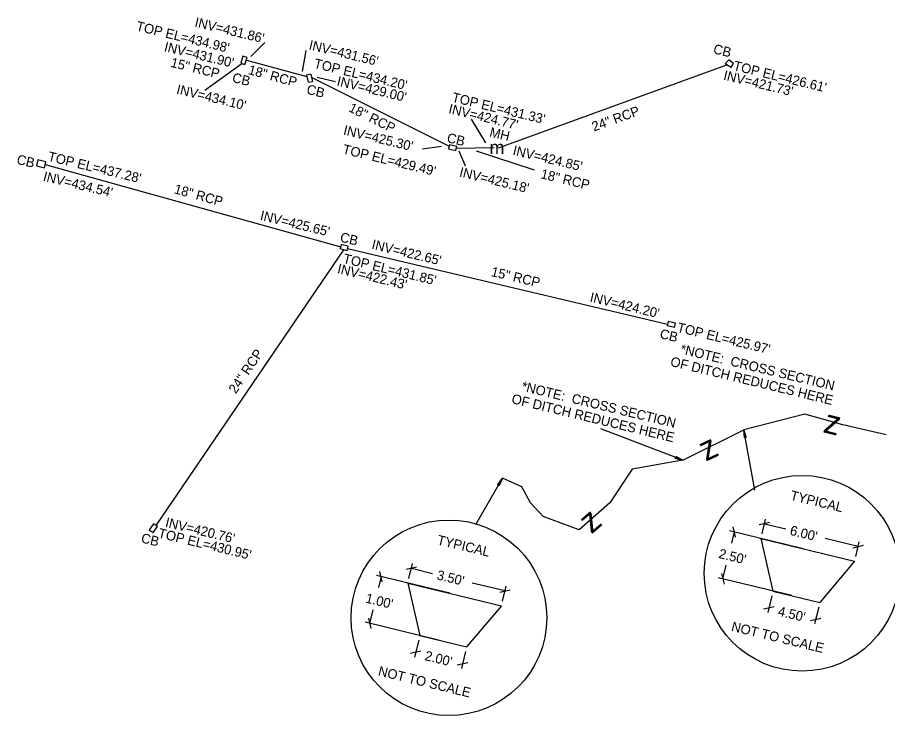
# Model space of a CAD drawing. Extents: x 1975859 to 1978323, y 778892 to 782836.
# Drawn here: x 1977393.8 to 1977755, y 779966.5 to 780256.5 of the extents above; entities that cross this region are included whole.
import ezdxf

# ---------------------------------------------------------------- set-up
doc = ezdxf.new("R2010")
doc.units = 0
for name, color, linetype in [('Exist Structure Minor Catch Basin', 7, 'Continuous'), ('Exist Structure Minor Catch Basin Text', 7, 'Continuous'), ('Exist Structure Minor Catch Basin Top Elevation', 7, 'Continuous'), ('Exist Structure Minor Pipes RCP 15 Inch', 7, 'Continuous'), ('Exist Structure Minor Pipes RCP 15 Inch Invert', 7, 'Continuous'), ('Exist Structure Minor Pipes RCP 15 Inch Text', 7, 'Continuous'), ('Exist Structure Minor Pipes RCP 18 Inch', 7, 'Continuous'), ('Exist Structure Minor Pipes RCP 18 Inch Invert', 7, 'Continuous'), ('Exist Structure Minor Pipes RCP 18 Inch Leader', 7, 'Continuous'), ('Exist Structure Minor Pipes RCP 18 Inch SizeText', 7, 'Continuous'), ('Exist Structure Minor Pipes RCP 18 Inch Text', 7, 'Continuous'), ('Exist Structure Minor Pipes RCP 24 Inch', 7, 'Continuous'), ('Exist Structure Minor Pipes RCP 24 Inch Invert', 7, 'Continuous'), ('Exist Structure Minor Pipes RCP 24 Inch Text', 7, 'Continuous'), ('Exist Structure Minor Storm Sewer Manhole CELL', 7, 'Continuous'), ('Exist Structure Minor Storm Sewer Manhole Text', 7, 'Continuous'), ('Exist Structure Minor Storm Sewer Manhole Top Elevation', 7, 'Continuous'), ('Scratch_Level_8', 7, 'Continuous')]:
    doc.layers.add(name, color=color, linetype=linetype)

msp = doc.modelspace()

# ---------------------------------------------------------------- linework, layer by layer
at = {"layer": 'Exist Structure Minor Catch Basin'}
for p, q in [((1977487.39, 780240.38), (1977486.53, 780237.46)), ((1977690.04, 780235.63), (1977687.58, 780237.2)), ((1977515.66, 780232.92), (1977516.32, 780229.9)), ((1977573.18, 780203.68), (1977576.18, 780202.99)), ((1977402.37, 780197.29), (1977401.8, 780194.88)), ((1977530.73, 780159.58), (1977527.73, 780160.29)), ((1977666.47, 780127.68), (1977663.48, 780128.42)), ((1977450.15, 780042.53), (1977451.93, 780045.03))]:
    msp.add_line(p, q, dxfattribs=at)
for points in [[(1977486.53, 780237.46), (1977488.22, 780236.92), (1977489.17, 780239.82), (1977487.39, 780240.38)], [(1977690.04, 780235.63), (1977691.03, 780237.33), (1977689.11, 780238.91), (1977687.58, 780237.2)], [(1977515.66, 780232.92), (1977513.82, 780232.52), (1977514.44, 780229.54), (1977516.32, 780229.9)], [(1977573.18, 780203.68), (1977572.78, 780201.9), (1977575.76, 780201.22), (1977576.18, 780202.99)], [(1977401.8, 780194.88), (1977405.1, 780194.06), (1977405.71, 780196.43), (1977402.37, 780197.29)], [(1977530.73, 780159.58), (1977531.14, 780161.45), (1977528.19, 780162.15), (1977527.73, 780160.29)], [(1977666.47, 780127.68), (1977666.91, 780129.55), (1977663.95, 780130.21), (1977663.48, 780128.42)], [(1977451.93, 780045.03), (1977450.38, 780046.19), (1977448.58, 780043.69), (1977450.15, 780042.53)]]:
    msp.add_lwpolyline(points, dxfattribs=at)
at = {"layer": 'Exist Structure Minor Pipes RCP 15 Inch'}
for p, q in [((1977471.64, 780226.29), (1977487, 780237.36)), ((1977663.62, 780128.87), (1977530.86, 780160.3))]:
    msp.add_line(p, q, dxfattribs=at)
at = {"layer": 'Exist Structure Minor Pipes RCP 18 Inch'}
for p, q in [((1977488.87, 780238.76), (1977513.94, 780231.92)), ((1977516.02, 780231.5), (1977573.03, 780202.94)), ((1977575.97, 780202.13), (1977591.66, 780202.39)), ((1977405.32, 780195.31), (1977528.02, 780161.12))]:
    msp.add_line(p, q, dxfattribs=at)
at = {"layer": 'Exist Structure Minor Pipes RCP 18 Inch Leader'}
for points in [[(1977490.68, 780240.3), (1977496.46, 780246.07)], [(1977512.16, 780234.03), (1977513.69, 780242.77)], [(1977518.23, 780231.69), (1977525.82, 780229.83)], [(1977588.19, 780204.44), (1977582.34, 780214.22)], [(1977569.85, 780202.88), (1977561.92, 780201.81)], [(1977577.07, 780201.1), (1977579.7, 780194.77)], [(1977584.26, 780201.07), (1977608.35, 780193.15)]]:
    msp.add_lwpolyline(points, dxfattribs=at)
at = {"layer": 'Exist Structure Minor Pipes RCP 24 Inch'}
for p, q in [((1977593.48, 780202.32), (1977688.3, 780236.71)), ((1977529.14, 780159.92), (1977451.29, 780045.45))]:
    msp.add_line(p, q, dxfattribs=at)
at = {"layer": 'Scratch_Level_8'}
for p, q in [((1977670.05, 780072.53), (1977635.9, 780085.62)), ((1977670.05, 780072.53), (1977695.32, 780085.18)), ((1977699.84, 780060.11), (1977695.32, 780085.18)), ((1977696.17, 780081.97), (1977695.65, 780081.87)), ((1977695.69, 780081.92), (1977695.85, 780082.23)), ((1977695.85, 780082.23), (1977695.76, 780081.89)), ((1977695.85, 780082.23), (1977696.12, 780082)), ((1977695.85, 780082.23), (1977696.07, 780081.95)), ((1977695.85, 780082.23), (1977695.97, 780081.93)), ((1977695.85, 780082.23), (1977695.85, 780081.91)), ((1977666.86, 780073.47), (1977667.05, 780073.97)), ((1977667.25, 780073.61), (1977666.89, 780073.57)), ((1977667.25, 780073.61), (1977666.92, 780073.5)), ((1977667.25, 780073.61), (1977666.93, 780073.67)), ((1977667.25, 780073.61), (1977666.97, 780073.78)), ((1977667.25, 780073.61), (1977667.01, 780073.86)), ((1977667.07, 780073.91), (1977667.25, 780073.61)), ((1977584.03, 780045.88), (1977595.14, 780065.04)), ((1977593.71, 780062.04), (1977593.25, 780062.31)), ((1977593.31, 780062.32), (1977593.64, 780062.45)), ((1977593.64, 780062.45), (1977593.35, 780062.25)), ((1977593.64, 780062.45), (1977593.43, 780062.2)), ((1977593.64, 780062.45), (1977593.53, 780062.15)), ((1977593.64, 780062.45), (1977593.62, 780062.09)), ((1977593.64, 780062.45), (1977593.69, 780062.11)), ((1977706.06, 780046.67), (1977701.7, 780045.66)), ((1977702.86, 780041.98), (1977704.35, 780048.11)), ((1977703.88, 780046.17), (1977712.68, 780044.03)), ((1977719.89, 780035.79), (1977689.36, 780043.2)), ((1977691.31, 780042.73), (1977690.19, 780038.14)), ((1977691.81, 780040.55), (1977690.81, 780044.91)), ((1977702.39, 780040.04), (1977741.27, 780030.61)), ((1977702.39, 780040.04), (1977707.4, 780018.24)), ((1977742.75, 780036.74), (1977729.07, 780040.06)), ((1977741.74, 780032.55), (1977743.22, 780038.68)), ((1977740.57, 780036.24), (1977744.93, 780037.24)), ((1977559.51, 780028.17), (1977555.15, 780027.17)), ((1977556.31, 780023.49), (1977557.8, 780029.62)), ((1977557.33, 780027.67), (1977566.13, 780025.54)), ((1977686.59, 780023.29), (1977687.97, 780028.95)), ((1977741.27, 780030.61), (1977726.83, 780013.53)), ((1977573.34, 780017.3), (1977542.81, 780024.71)), ((1977544.76, 780024.23), (1977543.64, 780019.65)), ((1977545.26, 780022.06), (1977544.26, 780026.41)), ((1977686.09, 780025.47), (1977687.09, 780021.11)), ((1977555.84, 780021.55), (1977594.72, 780012.12)), ((1977555.84, 780021.55), (1977560.85, 779999.75)), ((1977596.2, 780018.25), (1977582.52, 780021.56)), ((1977715.17, 780016.36), (1977684.65, 780023.76)), ((1977594.02, 780017.74), (1977598.38, 780018.75)), ((1977595.19, 780014.06), (1977596.67, 780020.19)), ((1977707.4, 780018.24), (1977726.83, 780013.53)), ((1977706.93, 780016.3), (1977705.22, 780009.28)), ((1977540.04, 780004.8), (1977541.42, 780010.46)), ((1977594.72, 780012.12), (1977580.28, 779995.04)), ((1977707.87, 780011.72), (1977703.52, 780010.72)), ((1977726.36, 780011.59), (1977724.66, 780004.57)), ((1977539.54, 780006.98), (1977540.54, 780002.62)), ((1977722.95, 780006.01), (1977727.31, 780007.01)), ((1977568.62, 779997.87), (1977538.1, 780005.27)), ((1977560.85, 779999.75), (1977580.28, 779995.04)), ((1977560.38, 779997.81), (1977558.67, 779990.79)), ((1977561.32, 779993.23), (1977556.97, 779992.23)), ((1977579.81, 779993.09), (1977578.11, 779986.07)), ((1977576.4, 779987.52), (1977580.76, 779988.52))]:
    msp.add_line(p, q, dxfattribs=at)
for points in [[(1977754.38, 780083.09), (1977736.42, 780087.22), (1977720.65, 780091.73), (1977695.32, 780085.18)], [(1977696.09, 780082.11), (1977695.32, 780085.18), (1977696.17, 780081.97), (1977696.12, 780082), (1977696.09, 780082.11), (1977695.85, 780082.23), (1977695.67, 780082.03), (1977695.69, 780081.92), (1977695.65, 780081.87), (1977695.32, 780085.18), (1977695.67, 780082.03)], [(1977696.17, 780081.97), (1977696.22, 780082.21), (1977695.32, 780085.18), (1977695.52, 780082.08), (1977695.65, 780081.87)], [(1977695.58, 780081.98), (1977695.32, 780085.18), (1977696.2, 780082.09)], [(1977695.34, 780085.01), (1977695.34, 780085.09), (1977695.37, 780085), (1977695.39, 780084.91), (1977695.35, 780085), (1977695.35, 780084.92), (1977695.36, 780084.82), (1977695.37, 780084.91), (1977695.41, 780084.82), (1977695.43, 780084.73), (1977695.39, 780084.81), (1977695.37, 780084.73), (1977695.38, 780084.64), (1977695.4, 780084.72), (1977695.46, 780084.64), (1977695.48, 780084.55), (1977695.42, 780084.63), (1977695.39, 780084.54), (1977695.4, 780084.45), (1977695.44, 780084.54), (1977695.5, 780084.45), (1977695.52, 780084.36), (1977695.45, 780084.44), (1977695.41, 780084.36), (1977695.42, 780084.27), (1977695.47, 780084.35), (1977695.55, 780084.27), (1977695.57, 780084.18), (1977695.49, 780084.26), (1977695.44, 780084.17), (1977695.45, 780084.08), (1977695.5, 780084.17), (1977695.59, 780084.09), (1977695.61, 780084), (1977695.52, 780084.08), (1977695.46, 780083.99), (1977695.47, 780083.89), (1977695.54, 780083.98), (1977695.64, 780083.91), (1977695.66, 780083.82), (1977695.55, 780083.89), (1977695.48, 780083.8), (1977695.49, 780083.71), (1977695.57, 780083.8), (1977695.68, 780083.73), (1977695.7, 780083.64), (1977695.59, 780083.71), (1977695.5, 780083.61), (1977695.51, 780083.52), (1977695.6, 780083.62), (1977695.73, 780083.55), (1977695.75, 780083.46), (1977695.62, 780083.52), (1977695.52, 780083.43), (1977695.53, 780083.33), (1977695.64, 780083.43), (1977695.77, 780083.37), (1977695.8, 780083.27), (1977695.65, 780083.34), (1977695.54, 780083.24), (1977695.55, 780083.15), (1977695.67, 780083.25), (1977695.82, 780083.18), (1977695.84, 780083.09), (1977695.69, 780083.15), (1977695.56, 780083.06), (1977695.57, 780082.96), (1977695.7, 780083.06), (1977695.86, 780083), (1977695.89, 780082.91), (1977695.73, 780082.97), (1977695.58, 780082.87), (1977695.59, 780082.78), (1977695.74, 780082.88), (1977695.91, 780082.82), (1977695.93, 780082.73), (1977695.75, 780082.79), (1977695.6, 780082.68), (1977695.61, 780082.59), (1977695.77, 780082.69), (1977695.95, 780082.64), (1977695.98, 780082.55), (1977695.79, 780082.6), (1977695.62, 780082.5), (1977695.63, 780082.4), (1977695.8, 780082.51), (1977696, 780082.46), (1977696.02, 780082.37), (1977695.82, 780082.42), (1977695.64, 780082.31), (1977695.65, 780082.22), (1977695.84, 780082.33), (1977696.04, 780082.27), (1977696.07, 780082.18), (1977695.85, 780082.23), (1977695.66, 780082.13)], [(1977670.05, 780072.53), (1977649.01, 780068.8), (1977639.65, 780054.82), (1977627.03, 780043.71), (1977612.03, 780049.15), (1977606.75, 780054.93), (1977603.18, 780061.49), (1977595.14, 780065.04)], [(1977667.02, 780073.47), (1977670.05, 780072.53), (1977666.86, 780073.47), (1977666.92, 780073.5), (1977667.02, 780073.47), (1977667.25, 780073.61), (1977667.17, 780073.86), (1977667.07, 780073.91), (1977667.05, 780073.97), (1977670.05, 780072.53), (1977667.17, 780073.86)], [(1977666.86, 780073.47), (1977667.04, 780073.3), (1977670.05, 780072.53), (1977667.3, 780073.97), (1977667.05, 780073.97)], [(1977667.17, 780073.97), (1977670.05, 780072.53), (1977666.95, 780073.39)], [(1977669.89, 780072.61), (1977669.96, 780072.57), (1977669.87, 780072.59), (1977669.78, 780072.62), (1977669.87, 780072.6), (1977669.81, 780072.65), (1977669.72, 780072.68), (1977669.79, 780072.63), (1977669.69, 780072.64), (1977669.6, 780072.67), (1977669.7, 780072.67), (1977669.64, 780072.72), (1977669.55, 780072.76), (1977669.61, 780072.7), (1977669.51, 780072.7), (1977669.42, 780072.73), (1977669.52, 780072.73), (1977669.47, 780072.8), (1977669.38, 780072.84), (1977669.44, 780072.77), (1977669.33, 780072.76), (1977669.24, 780072.78), (1977669.35, 780072.8), (1977669.3, 780072.88), (1977669.21, 780072.92), (1977669.26, 780072.83), (1977669.15, 780072.81), (1977669.06, 780072.84), (1977669.17, 780072.87), (1977669.13, 780072.96), (1977669.04, 780073), (1977669.09, 780072.9), (1977668.98, 780072.87), (1977668.89, 780072.89), (1977669, 780072.94), (1977668.96, 780073.04), (1977668.87, 780073.08), (1977668.91, 780072.97), (1977668.8, 780072.92), (1977668.71, 780072.95), (1977668.82, 780073), (1977668.79, 780073.12), (1977668.7, 780073.16), (1977668.74, 780073.04), (1977668.62, 780072.98), (1977668.53, 780073.01), (1977668.65, 780073.07), (1977668.62, 780073.2), (1977668.53, 780073.23), (1977668.56, 780073.1), (1977668.44, 780073.03), (1977668.35, 780073.06), (1977668.48, 780073.14), (1977668.45, 780073.27), (1977668.36, 780073.31), (1977668.39, 780073.17), (1977668.26, 780073.09), (1977668.17, 780073.12), (1977668.3, 780073.2), (1977668.28, 780073.35), (1977668.19, 780073.39), (1977668.21, 780073.24), (1977668.08, 780073.14), (1977667.99, 780073.17), (1977668.12, 780073.27), (1977668.11, 780073.43), (1977668.02, 780073.47), (1977668.04, 780073.3), (1977667.9, 780073.2), (1977667.81, 780073.23), (1977667.95, 780073.33), (1977667.94, 780073.51), (1977667.85, 780073.55), (1977667.86, 780073.37), (1977667.72, 780073.25), (1977667.63, 780073.28), (1977667.78, 780073.4), (1977667.77, 780073.59), (1977667.68, 780073.63), (1977667.69, 780073.44), (1977667.54, 780073.31), (1977667.46, 780073.34), (1977667.6, 780073.47), (1977667.6, 780073.67), (1977667.51, 780073.7), (1977667.51, 780073.51), (1977667.37, 780073.36), (1977667.28, 780073.39), (1977667.43, 780073.54), (1977667.43, 780073.74), (1977667.34, 780073.78), (1977667.34, 780073.57), (1977667.19, 780073.42), (1977667.1, 780073.45), (1977667.25, 780073.61), (1977667.26, 780073.82)], [(1977593.74, 780062.2), (1977595.14, 780065.04), (1977593.71, 780062.04), (1977593.69, 780062.11), (1977593.74, 780062.2), (1977593.64, 780062.45), (1977593.37, 780062.41), (1977593.31, 780062.32), (1977593.25, 780062.31), (1977595.14, 780065.04), (1977593.37, 780062.41)], [(1977593.71, 780062.04), (1977593.9, 780062.19), (1977595.14, 780065.04), (1977593.28, 780062.55), (1977593.25, 780062.31)], [(1977593.27, 780062.43), (1977595.14, 780065.04), (1977593.81, 780062.12)], [(1977595.05, 780064.9), (1977595.1, 780064.96), (1977595.06, 780064.88), (1977595.02, 780064.79), (1977595.05, 780064.88), (1977594.99, 780064.82), (1977594.94, 780064.74), (1977595, 780064.8), (1977594.98, 780064.71), (1977594.93, 780064.62), (1977594.95, 780064.72), (1977594.89, 780064.67), (1977594.84, 780064.59), (1977594.91, 780064.64), (1977594.89, 780064.54), (1977594.85, 780064.46), (1977594.86, 780064.56), (1977594.78, 780064.51), (1977594.73, 780064.43), (1977594.81, 780064.48), (1977594.81, 780064.37), (1977594.77, 780064.29), (1977594.77, 780064.4), (1977594.68, 780064.36), (1977594.63, 780064.28), (1977594.72, 780064.32), (1977594.73, 780064.21), (1977594.69, 780064.12), (1977594.67, 780064.23), (1977594.58, 780064.2), (1977594.52, 780064.12), (1977594.63, 780064.15), (1977594.64, 780064.04), (1977594.6, 780063.95), (1977594.58, 780064.07), (1977594.47, 780064.04), (1977594.42, 780063.97), (1977594.53, 780063.99), (1977594.56, 780063.87), (1977594.52, 780063.79), (1977594.48, 780063.91), (1977594.37, 780063.89), (1977594.31, 780063.81), (1977594.44, 780063.83), (1977594.48, 780063.7), (1977594.44, 780063.62), (1977594.39, 780063.75), (1977594.26, 780063.73), (1977594.21, 780063.66), (1977594.34, 780063.67), (1977594.39, 780063.53), (1977594.35, 780063.45), (1977594.3, 780063.59), (1977594.16, 780063.58), (1977594.1, 780063.5), (1977594.25, 780063.51), (1977594.31, 780063.37), (1977594.27, 780063.28), (1977594.2, 780063.42), (1977594.05, 780063.42), (1977594, 780063.35), (1977594.16, 780063.34), (1977594.23, 780063.2), (1977594.19, 780063.11), (1977594.11, 780063.26), (1977593.95, 780063.27), (1977593.9, 780063.19), (1977594.06, 780063.18), (1977594.14, 780063.03), (1977594.1, 780062.95), (1977594.02, 780063.1), (1977593.84, 780063.11), (1977593.79, 780063.04), (1977593.97, 780063.02), (1977594.06, 780062.86), (1977594.02, 780062.78), (1977593.92, 780062.94), (1977593.74, 780062.96), (1977593.69, 780062.88), (1977593.87, 780062.86), (1977593.98, 780062.7), (1977593.94, 780062.61), (1977593.83, 780062.78), (1977593.63, 780062.8), (1977593.58, 780062.72), (1977593.78, 780062.7), (1977593.9, 780062.53), (1977593.85, 780062.44), (1977593.73, 780062.61), (1977593.53, 780062.65), (1977593.48, 780062.57), (1977593.69, 780062.53), (1977593.81, 780062.36), (1977593.77, 780062.28), (1977593.64, 780062.45), (1977593.43, 780062.49)]]:
    msp.add_lwpolyline(points, dxfattribs=at)
for centre in [(1977719.47, 780025.6), (1977572.92, 780007.11)]:
    msp.add_circle(centre, 40.62, dxfattribs=at)

# ---------------------------------------------------------------- texts
at = {"layer": 'Exist Structure Minor Catch Basin Text'}
for rotation, p in [(346.3665, (1977682.33, 780241.61)), (346.3665, (1977482.71, 780229.7)), (346.3665, (1977513.58, 780224.8)), (346.3665, (1977571.81, 780204.72)), (346.3665, (1977393.26, 780195.72)), (346.6781, (1977527.46, 780163.4)), (346.3665, (1977660.16, 780123.32)), (346.3665, (1977444.88, 780038.47))]:
    msp.add_text('CB', height=4, rotation=rotation, dxfattribs=at).set_placement(p)
at = {"layer": 'Exist Structure Minor Catch Basin Top Elevation'}
for s, p in [("TOP EL=434.98'", (1977442.85, 780251.09)), ("TOP EL=434.20'", (1977516.64, 780235.58)), ("TOP EL=426.61'", (1977690.68, 780234.63)), ("TOP EL=437.28'", (1977406.24, 780196.94)), ("TOP EL=429.49'", (1977528.51, 780199.96)), ("TOP EL=431.85'", (1977528.71, 780154.56)), ("TOP EL=425.97'", (1977667.33, 780125.94)), ("TOP EL=430.95'", (1977451.96, 780040.53))]:
    msp.add_text(s, height=4, rotation=346.3665, dxfattribs=at).set_placement(p)
at = {"layer": 'Exist Structure Minor Pipes RCP 15 Inch Invert'}
for s, p in [("INV=431.90'", (1977454.49, 780242.5)), ("INV=434.10'", (1977459.59, 780224.85)), ("INV=422.65'", (1977540.59, 780160.41)), ("INV=424.20'", (1977631.15, 780138.49))]:
    msp.add_text(s, height=4, rotation=346.3665, dxfattribs=at).set_placement(p)
at = {"layer": 'Exist Structure Minor Pipes RCP 15 Inch Text'}
for rotation, p in [(346.3665, (1977457.16, 780235.96)), (346.6781, (1977590.14, 780149.09))]:
    msp.add_text('15" RCP', height=4, rotation=rotation, dxfattribs=at).set_placement(p)
at = {"layer": 'Exist Structure Minor Pipes RCP 18 Inch Invert'}
for s, p in [("INV=431.86'", (1977467.15, 780252.7)), ("INV=431.56'", (1977514.53, 780243.24)), ("INV=429.00'", (1977526.15, 780228.27)), ("INV=424.77'", (1977572.5, 780216.76)), ("INV=425.30'", (1977528.85, 780207.86)), ("INV=425.18'", (1977576.99, 780190.43)), ("INV=434.54'", (1977404.26, 780188.68)), ("INV=425.65'", (1977494.3, 780172.43))]:
    msp.add_text(s, height=4, rotation=346.3665, dxfattribs=at).set_placement(p)
at = {"layer": 'Exist Structure Minor Pipes RCP 18 Inch SizeText'}
msp.add_text('18" RCP', height=4, rotation=346.3665, dxfattribs=at).set_placement((1977610.73, 780189.72))
at = {"layer": 'Exist Structure Minor Pipes RCP 18 Inch Text'}
for rotation, p in [(344.7549, (1977489.33, 780232.98)), (333.3891, (1977530.97, 780217.61)), (344.4301, (1977458.58, 780183.48))]:
    msp.add_text('18" RCP', height=4, rotation=rotation, dxfattribs=at).set_placement(p)
at = {"layer": 'Exist Structure Minor Pipes RCP 24 Inch Invert'}
for s, p in [("INV=421.73'", (1977686.57, 780230.67)), ("INV=424.85'", (1977599.15, 780199.48)), ("INV=422.43'", (1977526.35, 780150.36)), ("INV=420.76'", (1977454.94, 780044.97))]:
    msp.add_text(s, height=4, rotation=346.3665, dxfattribs=at).set_placement(p)
at = {"layer": 'Exist Structure Minor Pipes RCP 24 Inch Text'}
for rotation, p in [(19.9339, (1977633.07, 780209.02)), (55.7774, (1977484.45, 780099.9))]:
    msp.add_text('24" RCP', height=4, rotation=rotation, dxfattribs=at).set_placement(p)
at = {"layer": 'Exist Structure Minor Storm Sewer Manhole CELL'}
msp.add_text('m', height=5.5, dxfattribs=at).set_placement((1977589.8, 780199.73))
at = {"layer": 'Exist Structure Minor Storm Sewer Manhole Text'}
msp.add_text('MH', height=4, rotation=346.3665, dxfattribs=at).set_placement((1977589.51, 780207.05))
at = {"layer": 'Exist Structure Minor Storm Sewer Manhole Top Elevation'}
msp.add_text("TOP EL=431.33'", height=4, rotation=346.3665, dxfattribs=at).set_placement((1977573.89, 780221.49))
at = {"layer": 'Scratch_Level_8'}
for s, height, rotation, p in [('*NOTE:  CROSS SECTION', 4, 346.3665, (1977668.63, 780116.95)), (' OF DITCH REDUCES HERE', 4, 346.3665, (1977663.08, 780112.12)), ('*NOTE:  CROSS SECTION', 4, 346.3665, (1977602.74, 780101.48)), (' OF DITCH REDUCES HERE', 4, 346.3665, (1977597.19, 780096.65)), ('z', 10, 345.9642, (1977727.77, 780084.27)), ('z', 10, 25.3983, (1977679.5, 780071.91)), ('TYPICAL', 4, 346.3666, (1977714.3, 780056.17)), ('z', 10, 40.3887, (1977632.02, 780041.67)), ("6.00'", 4, 346.3666, (1977714.15, 780041.62)), ('TYPICAL', 4, 346.3666, (1977567.75, 780037.68)), ("2.50'", 4, 346.3666, (1977684.59, 780032.01)), ("3.50'", 4, 346.3666, (1977567.6, 780023.12)), ("1.00'", 4, 346.3666, (1977538.04, 780013.51)), ("4.50'", 4, 346.3666, (1977709.17, 780008.09)), ('NOT TO SCALE', 4, 346.3666, (1977689.84, 780001.73)), ("2.00'", 4, 346.3666, (1977562.62, 779989.6)), ('NOT TO SCALE', 4, 346.3666, (1977543.29, 779983.23))]:
    msp.add_text(s, height=height, rotation=rotation, dxfattribs=at).set_placement(p)

doc.saveas('drawing.dxf')
